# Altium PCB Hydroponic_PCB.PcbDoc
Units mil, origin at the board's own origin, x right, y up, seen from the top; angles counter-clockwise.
Board outline 3600 x 3940 mil, 4 copper layers (SIG 1, GND, SIG 2, PWR), stack 62.508 mil thick; 31 components, 21 nets, 122 pads, 71 vias.
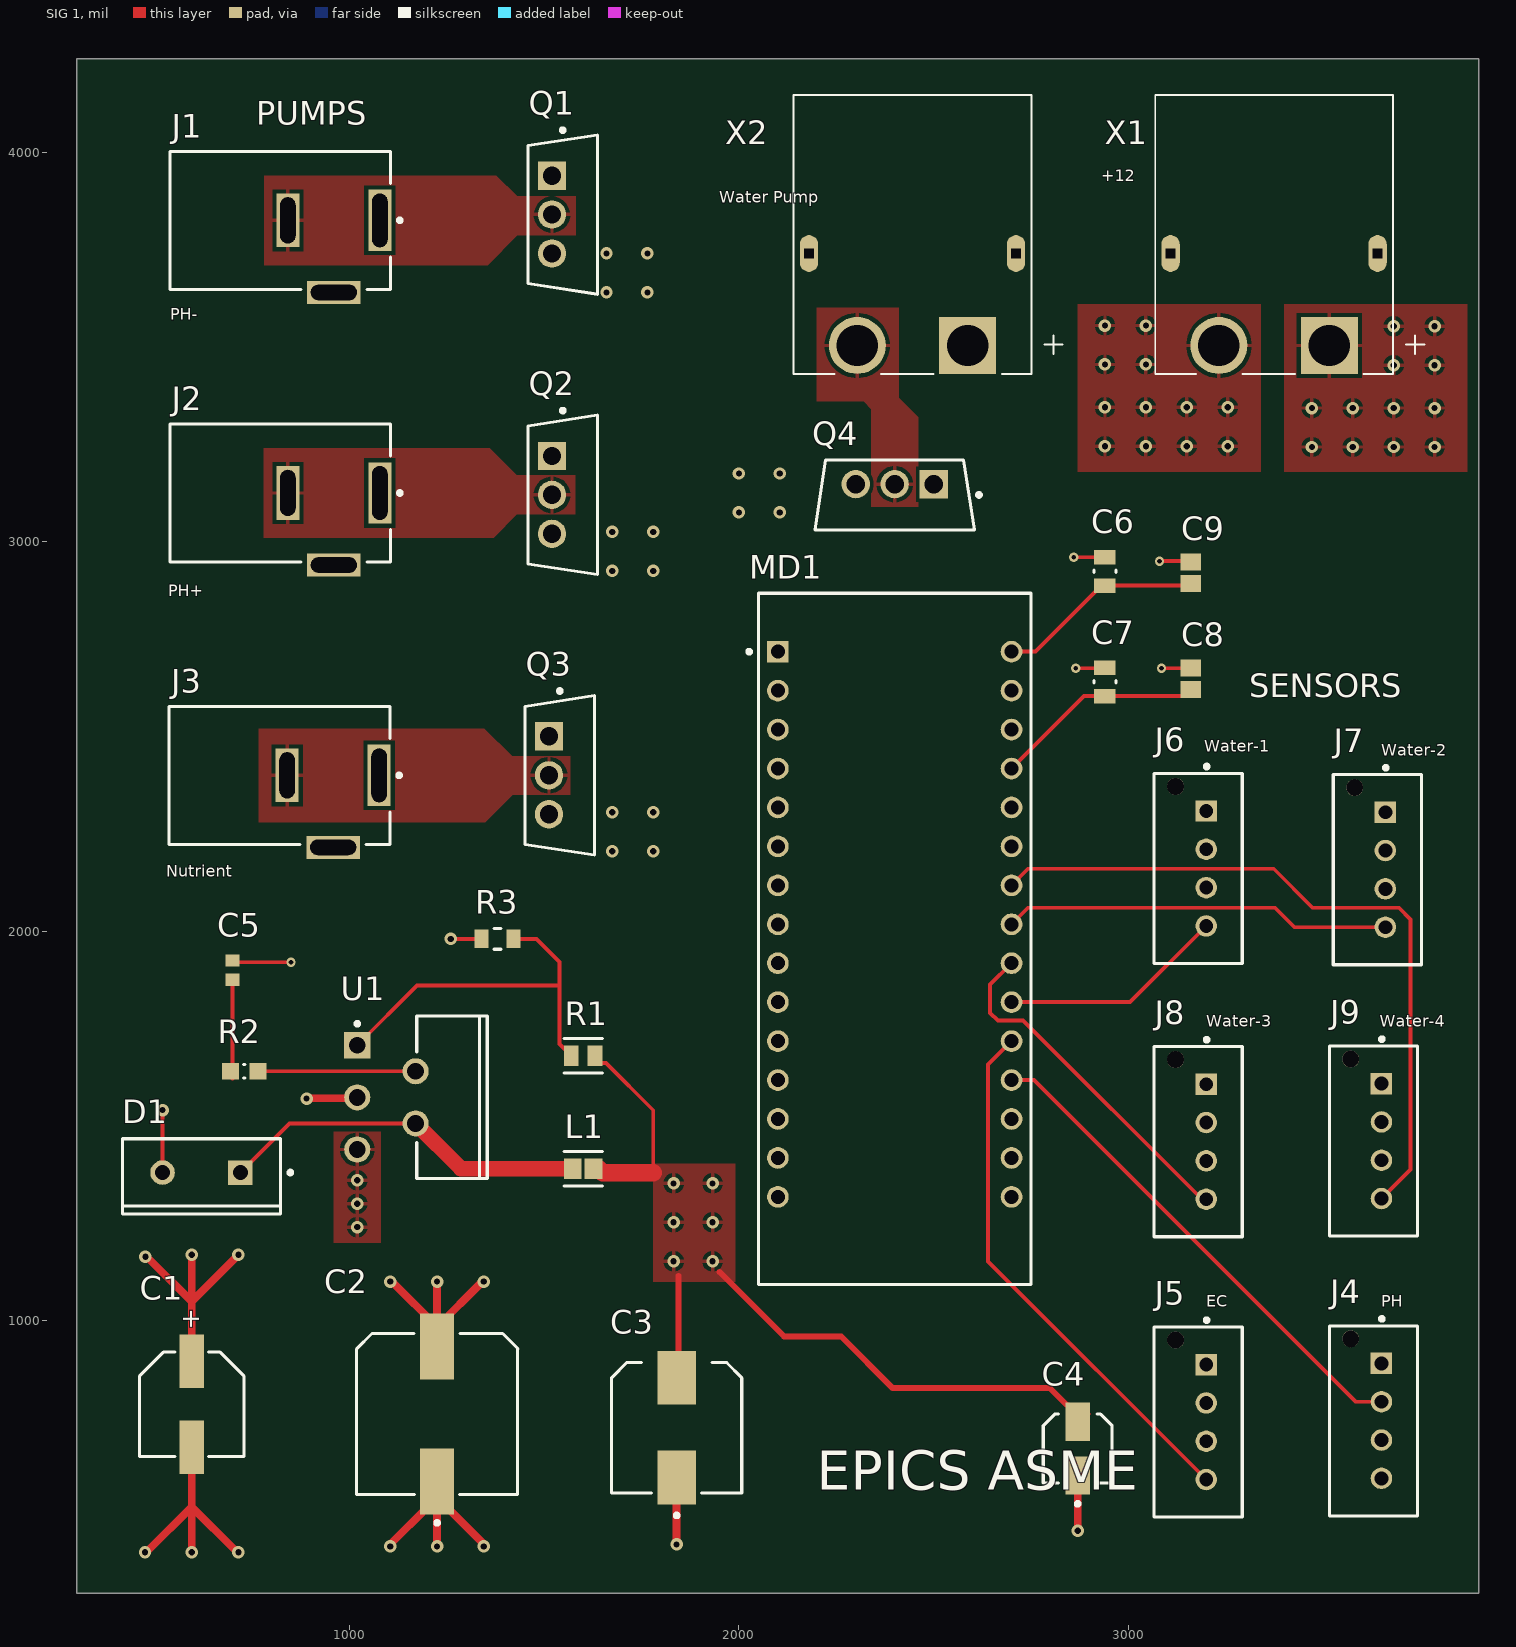
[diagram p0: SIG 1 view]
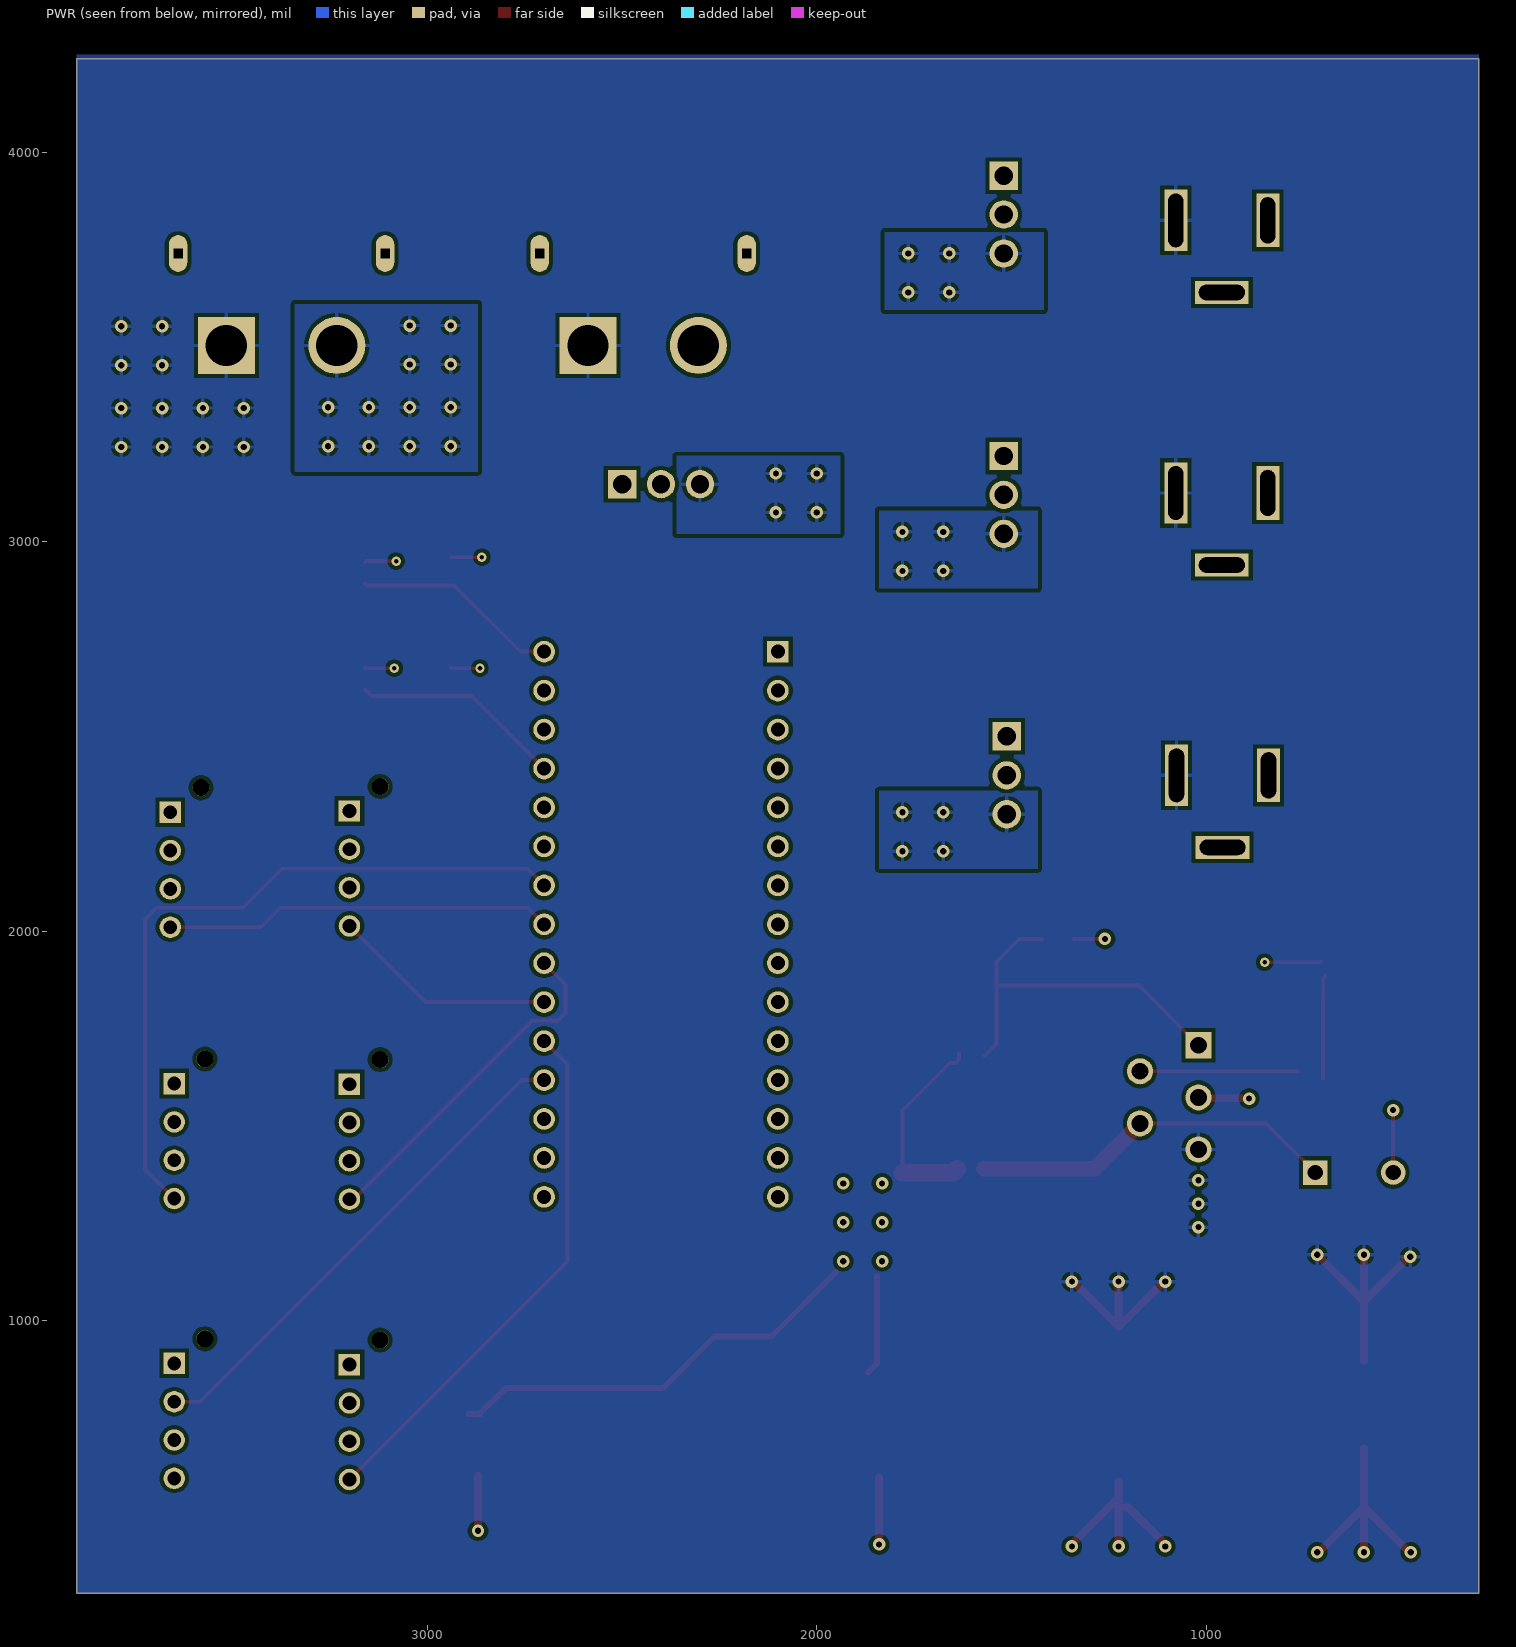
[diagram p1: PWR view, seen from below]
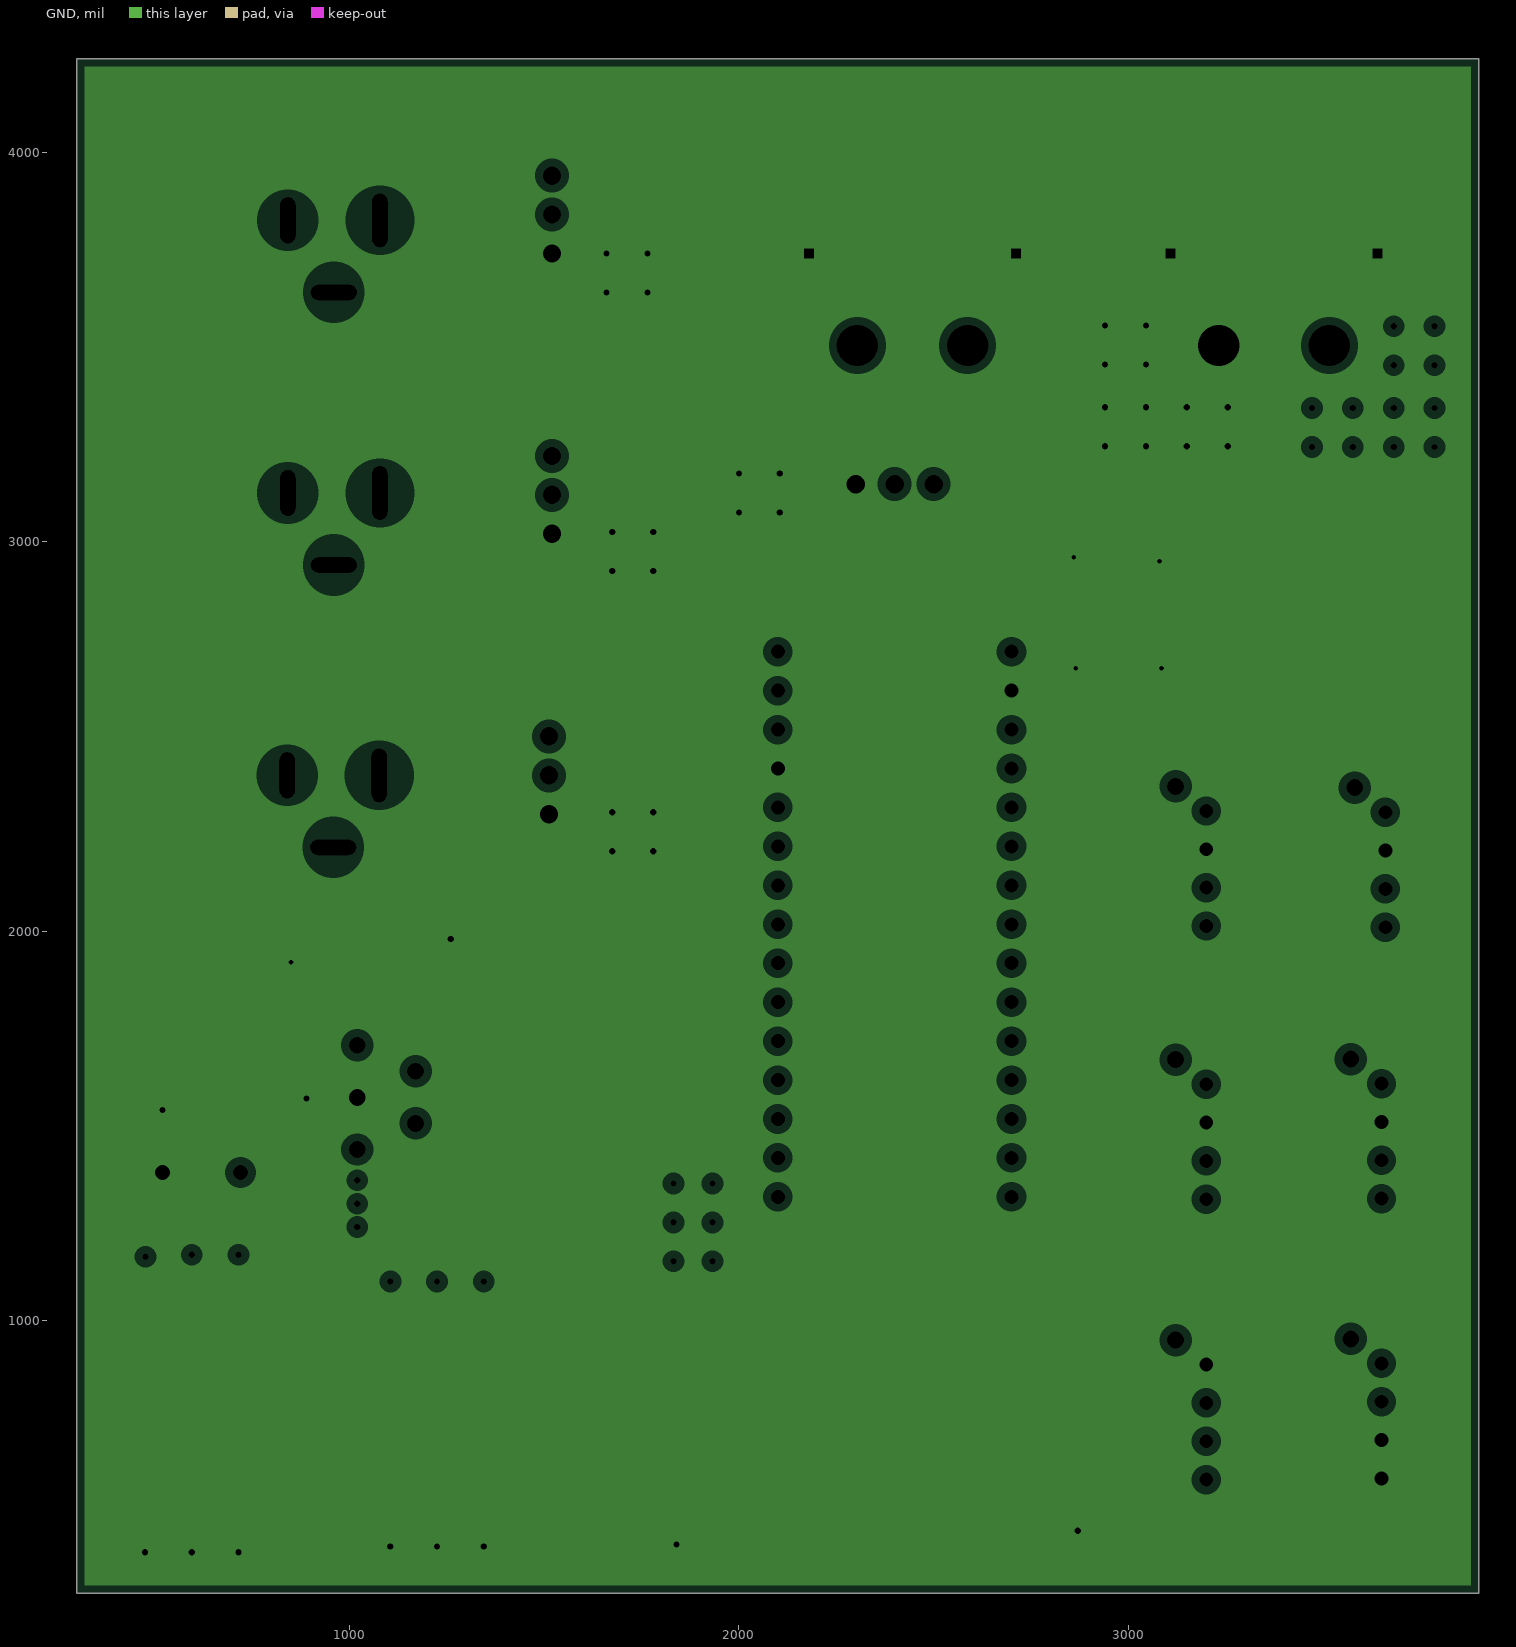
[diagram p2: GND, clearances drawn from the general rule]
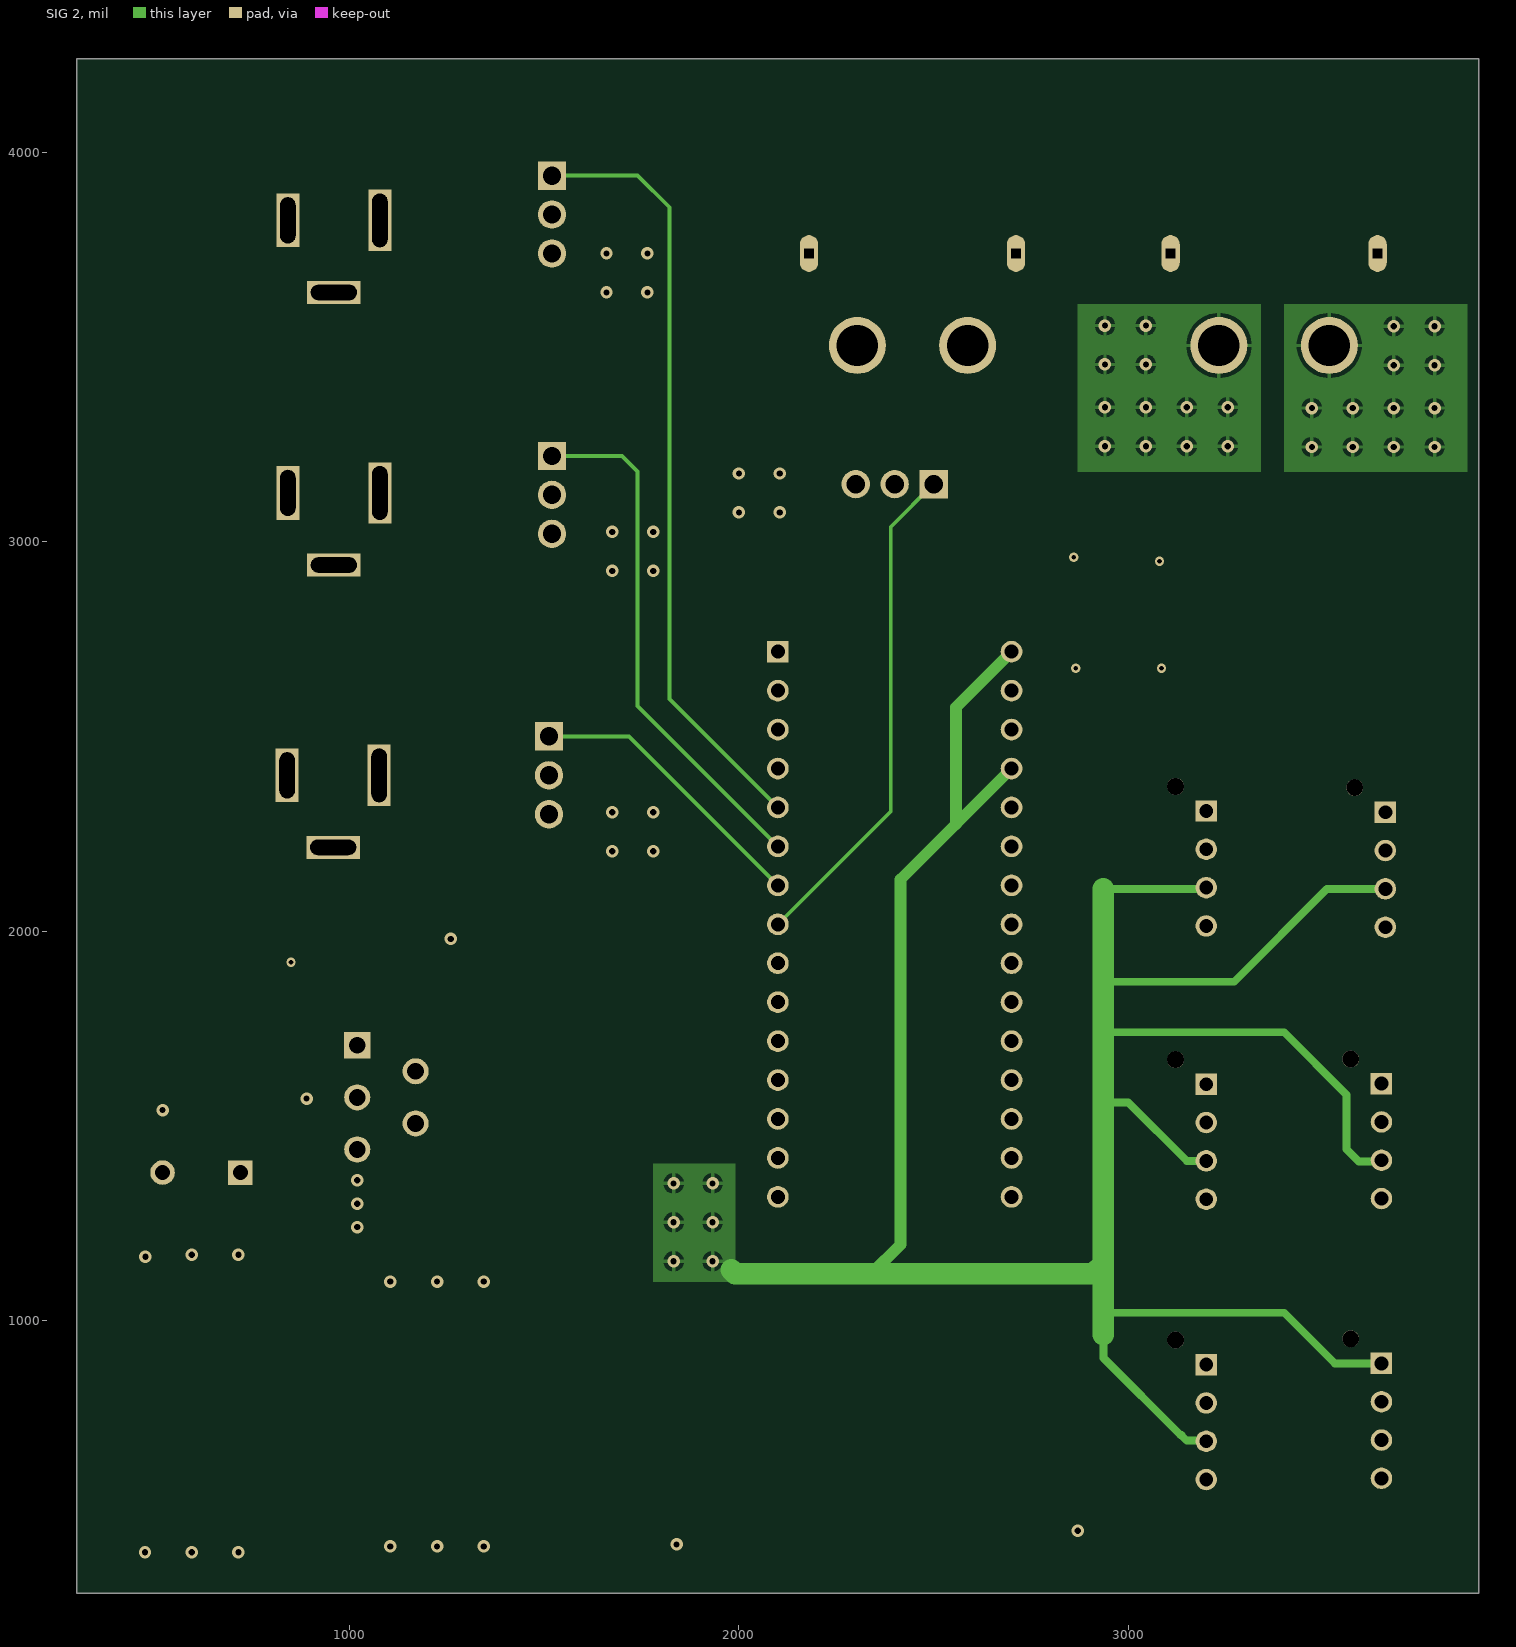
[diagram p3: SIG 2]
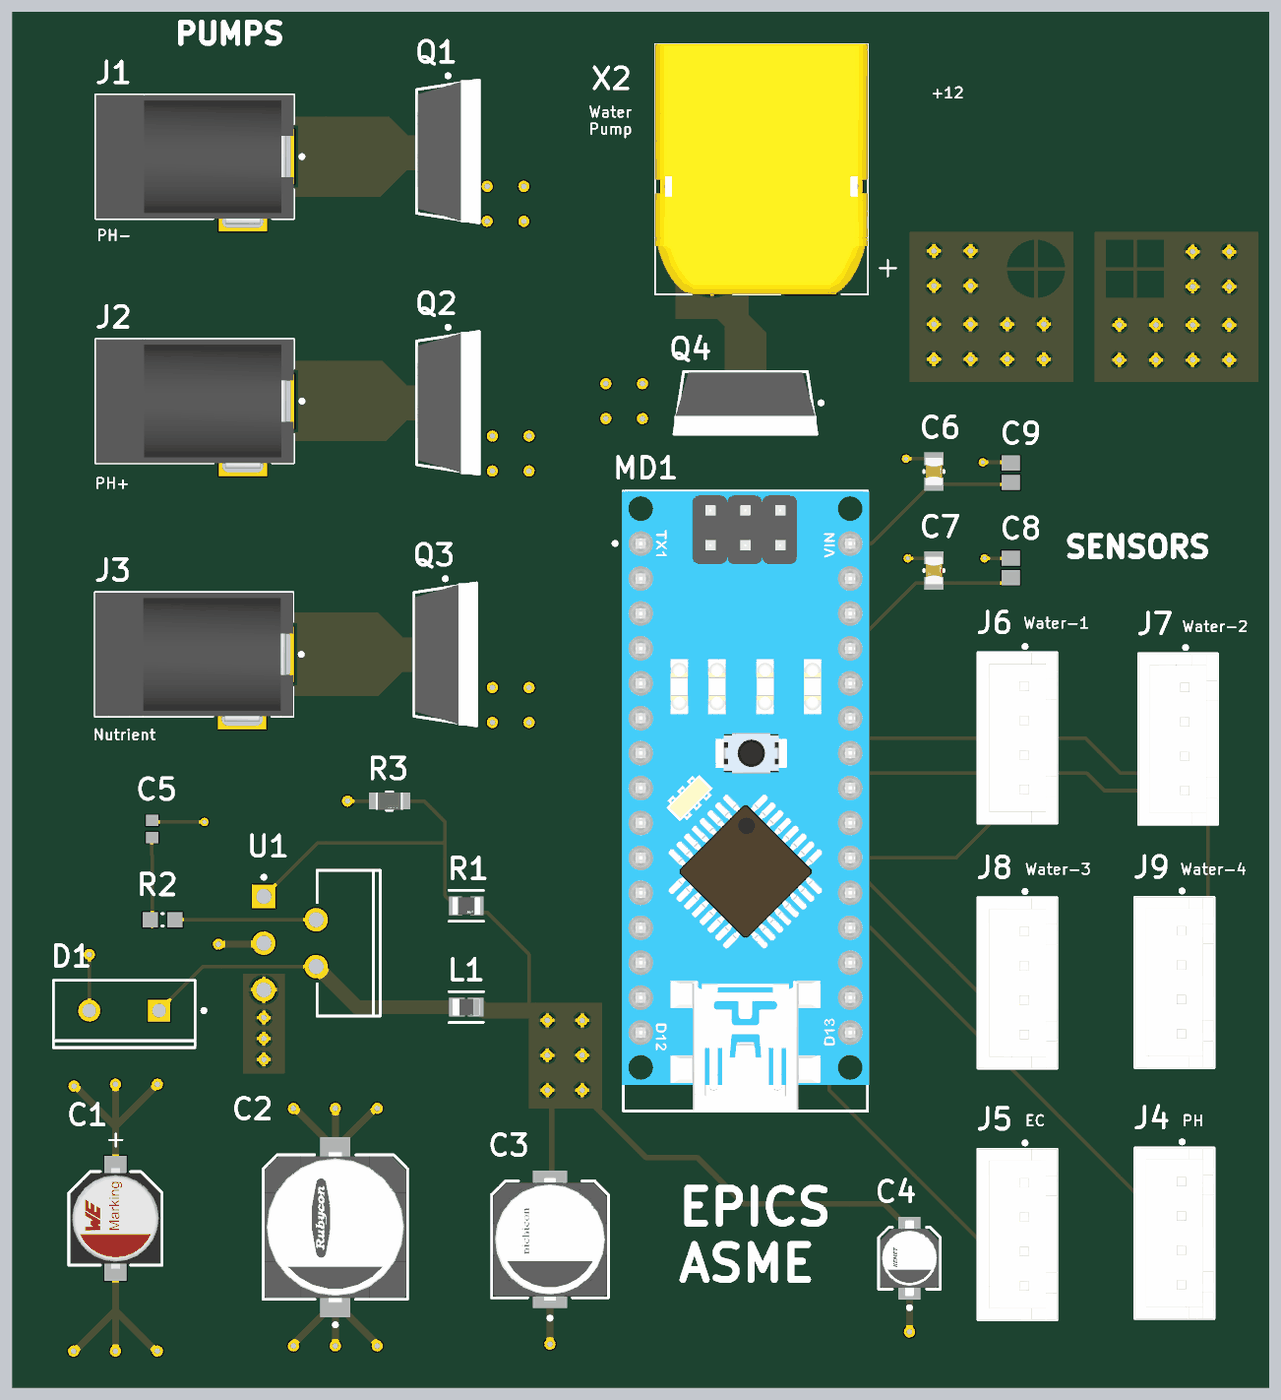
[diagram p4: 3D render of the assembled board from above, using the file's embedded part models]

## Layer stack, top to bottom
Top Solder: solder mask 0.4, Solder Resist, Dk 3.5
SIG 1: signal copper 1.4
Dielectric 1: prepreg 8.2, 7628, Dk 4.5
GND: plane copper 0.689, net GND
Dielectric 2: core 41.93, S1000-2M, Dk 4.3
SIG 2: signal copper 0.689
Dielectric 3: prepreg 8.2, 7628, Dk 4.5
PWR: signal copper 1.4
Bottom Solder: solder mask 0.4, Solder Resist, Dk 3.5

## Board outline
300,300 300,4240 3900,4240 3900,300

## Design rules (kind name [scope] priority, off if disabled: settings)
Clearance Components [InComponent('L1') OR InComponent('C5') OR InComponent('C8') OR InComponent('C9') OR InComponent('R2')] p1: gap=2 ignorepadtopadclearanceinfootprint=FALSE
Clearance GND_clearance [OnLayer('GND')] p2: gap=10 ignorepadtopadclearanceinfootprint=FALSE
Clearance [All] p3: gap=10 ignorepadtopadclearanceinfootprint=FALSE
HoleSize [All] p1: absolutevalues=TRUE maxlimit=150 minlimit=1 maxpercent=80.000 minpercent=20.000
MinimumSolderMaskSliver [All] p1: minsoldermaskwidth=3
PlaneClearance [All] p1: clearance=20
PlaneConnect [All] p1: planeconnectstyle=Relief reliefexpansion=20 reliefentries=4 reliefconductorwidth=10 reliefairgap=10
PolygonConnect [All] p1: connectstyle=Relief reliefconductorwidth=10 reliefentries=4 polygonreliefangle="90 Angle" airgapwidth=10
RoutingVias [All] p1: holewidth=12 width=24 viastyle="Through Hole" minholewidth=10 minwidth=18 maxholewidth=28 maxwidth=50
SilkToSolderMaskClearance [IsPad] p1: minsilkscreentomaskgap=3 clearancetoexposedcopper=TRUE
SolderMaskExpansion [All] p1: expansion=4 istentingtop=FALSE
SupplyNets "Schematic Supply Nets_2" [InNet('+12')] p1: voltage=0.000
SupplyNets "Schematic Supply Nets_1" [InNet('+5')] p2: voltage=0.000
SupplyNets "Schematic Supply Nets" [InNet('GND')] p3: voltage=0.000
Width [All] p1: maxlimit=100 minlimit=10 preferedwidth=10
25 further rules are at their usual default settings.

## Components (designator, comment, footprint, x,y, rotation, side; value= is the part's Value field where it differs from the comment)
C1 "220 uF" WCAP-ASLL_D6.3H7.7 595,785 r90 top
C2 "100 uF" FP-TGV10X10_5-MFG 1225,760 r90 top
C3 "47 uF" FP-UUX1H470MNL6GS-MFG 1840,725 r90 top
C4 "10 uF" FP-EDK9B-MFG 2870,671.1 r90 top value=10uF
C5 "10 nF" CAPC1608X87X35LL15T15 700,1900 r90 top
C6 "1 uF" FP-CC0805-0_85-MFG 2940,2923.58 r90 top
C7 "1 uF" FP-CC0805-0_85-MFG 2940,2640 r90 top
C8 "100 nF" CAPC2013X140X50LL20T25 3160,2647.56 r270 top
C9 "100 nF" CAPC2013X140X50LL20T25 3160,2920 r270 top
D1 "MBR745G" ONSC-TO-220-2-221B-04_E 620,1380 r270 top
J1 "PJ-002A" CUI-PJ-002A_V 960,3825.04 r180 top
J2 "PJ-002A" CUI-PJ-002A_V 960,3125.04 r180 top
J3 "PJ-002A" CUI-PJ-002A_V 958.11,2400 r180 top
J4 "PH Sensor Connector" FP-B4B-XH-AM_LF_SN-MFG 3629.33,742.36 r90 top
J5 "EC Sensor Connector" FP-B4B-XH-AM_LF_SN-MFG 3179.33,739.21 r90 top
J6 "Water sensor 1" FP-B4B-XH-AM_LF_SN-MFG 3179.33,2160.79 r90 top
J7 "Water sensor 3" FP-B4B-XH-AM_LF_SN-MFG 3639.33,2157.64 r90 top
J8 "Water sensor 2" FP-B4B-XH-AM_LF_SN-MFG 3179.33,1459.21 r90 top
J9 "Water sensor 4" FP-B4B-XH-AM_LF_SN-MFG 3629.33,1460.79 r90 top
L1 "100 uH" FP-LQM21DH_70-IPC_C 1600,1390 r0 top
MD1 "A000005" FP-A000005-MFG 2400,1980 r0 top
Q1 "IRLZ44NPbF" FP-PG-TO220-3-MFG 1547.76,3840 r0 top
Q2 "IRLZ44NPbF" FP-PG-TO220-3-MFG 1547.76,3120 r0 top
Q3 "IRLZ44NPbF" FP-PG-TO220-3-MFG 1540,2400 r0 top
Q4 "IRLZ44NPbF" FP-PG-TO220-3-MFG 2400,3120 r270 top
R1 "2.8k" FP-RG2012-IPC_C 1600,1680 r0 top
R2 "2.7k" RESC0603(1608)_M 730,1640 r0 top value="2700.00 Ohm"
R3 "2.2k" FP-AC0805-MFG 1380,1980 r0 top value=2.2KΩ
U1 "LT1076IT" LT-T-5-S 1095,1573.07 r0 top
X1 "X1" PCBComponent_1 4890.16,1901.26 r180 top
X2 "X2" PCBComponent_1 3961.65,1901.26 r180 top

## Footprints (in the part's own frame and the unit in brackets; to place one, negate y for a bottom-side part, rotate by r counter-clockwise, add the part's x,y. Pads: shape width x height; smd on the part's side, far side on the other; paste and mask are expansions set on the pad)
CAPC1608X87X35LL15T15 [mm] "Chip Capacitor, 2-Leads, Body 1.60x0.80mm, IPC High Density"
  rect 0.8x0.9 smd: 1(-0.625,0) 2(0.625,0)
  body extent -0.87,-0.48 0.87,0.48, height 0.87
CAPC2013X140X50LL20T25 [mm] "Chip Capacitor, 2-Leads, Body 2.00x1.25mm, IPC High Density"
  rect 1.1x1.35 smd: 1(-0.7,0) 2(0.7,0)
  body extent -1.1,-0.72 1.1,0.72, height 1.4
CUI-PJ-002A_V [mm] "THD, 3-Leads, Body 14.4x9mm, Height 11mm"
  rect 1.5x4 hole 1 slot 3.5 at 90 deg: 1(-3,0)
  rect 1.5x3.5 hole 1 slot 3 at 90 deg: 2(3,0)
  rect 3.5x1.5 hole 1 slot 3 at 0 deg: 3(0,4.7)
  silkscreen extent -4.43,-4.5 10.7,4.5, body extent -3.7,-4.5 10.7,4.9, height 11
FP-A000005-MFG [mil]
  rect 55.67x55.67 hole 35.98 paste-99999 mask+0: 1(-300,737.5)
  round 55.67 hole 35.98 paste-99999 mask+0: 2(-300,637.5) 3(-300,537.5) 4(-300,437.5) 5(-300,337.5) 6(-300,237.5) 7(-300,137.5) 8(-300,37.5) 9(-300,-62.5) 10(-300,-162.5) 11(-300,-262.5) 12(-300,-362.5) 13(-300,-462.5) 14(-300,-562.5) 15(-300,-662.5) 16(300,-662.5) 17(300,-562.5) 18(300,-462.5) 19(300,-362.5) 20(300,-262.5) 21(300,-162.5) 22(300,-62.5) 23(300,37.5) 24(300,137.5) 25(300,237.5) 26(300,337.5) 27(300,437.5) 28(300,537.5) 29(300,637.5) 30(300,737.5)
  silkscreen extent -379,-888 350,888, body extent -354,-891 354,891, height 10
FP-AC0805-MFG [mm]
  rect 0.9x1.2 smd paste+0 mask+0: 1(-1.05,0) 2(1.05,0)
  silkscreen extent -0.23,-0.67 0.23,0.67, body extent -1.6,-0.77 1.6,0.77, height 0.25
FP-B4B-XH-AM_LF_SN-MFG [mm]
  rect 1.4x1.4 hole 0.9 paste-2539.97 mask+0: 1(3.75,-0.525)
  round 1.4 hole 0.9 paste-2539.97 mask+0: 2(1.25,-0.525) 3(-1.25,-0.525) 4(-3.75,-0.525)
  round 1.1 hole 1.1 unplated paste-2539.97 mask+0: ""(5.35,1.475)
  silkscreen extent -6.2,-2.88 6.77,2.88, body extent -6.3,-2.98 6.3,2.98, height 0.25
FP-CC0805-0_85-MFG [mm]
  rect 0.95x1.4 smd paste+0 mask+0: 1(-0.925,0) 2(0.925,0)
  silkscreen extent -0.08,-0.72 0.08,0.72, body extent -1.6,-1.05 1.6,1.05, height 0.25
FP-EDK9B-MFG [mm]
  rect 2.5x1.6 smd paste+0 mask+0: 1(-1.75,0) 2(1.75,0)
  silkscreen extent -3.72,-2.25 2.25,2.25, body extent -3.25,-2.5 3.25,2.5, height 0.25
FP-LQM21DH_70-IPC_C [mil]
  rect 45.45x53.39 smd paste+0 mask+0: 1(-26.61,0) 2(26.61,0)
  silkscreen extent -49,-44 49,44, body extent -53,-32 53,32, height 10
FP-PG-TO220-3-MFG [mm]
  rect 1.85x1.85 hole 1.2 paste-2539.97 mask+0: 1(-0.705,2.54)
  round 1.85 hole 1.2 paste-2539.97 mask+0: 2(-0.705,0) 3(-0.705,-2.54)
  silkscreen extent -2.27,-5.2 2.27,5.62, body extent -2.37,-5.55 2.37,5.55, height 0.25
FP-RG2012-IPC_C [mil]
  rect 37.59x53.39 smd paste+0 mask+0: 1(-30.54,0) 2(30.54,0)
  silkscreen extent -49,-44 49,44, body extent -53,-32 53,32, height 10
FP-TGV10X10_5-MFG [mm]
  rect 4.3x2.2 smd paste+0 mask+0: 1(-4.4,0) 2(4.4,0)
  silkscreen extent -7.22,-5.28 5.25,5.25, body extent -6.8,-5.5 6.8,5.5, height 0.25
FP-UUX1H470MNL6GS-MFG [mm]
  rect 3.5x2.5 smd paste+0 mask+0: 1(-3.25,0) 2(3.25,0)
  silkscreen extent -5.85,-4.25 4.26,4.25, body extent -5.25,-4.5 5.25,4.5, height 0.25
LT-T-5-S [mm] "FM, 5-Leads, Body 10.55x4.6mm, Pitch 1.7mm"
  rect 1.7x1.7 hole 1.1: 1(-1.905,3.4)
  round 1.7 hole 1.1: 2(1.905,1.7) 3(-1.905,0) 4(1.905,-1.7) 5(-1.905,-3.4)
  silkscreen extent -2.03,-5.3 6.58,5.3, body extent -2.13,-5.27 6.58,5.28, height 22.23
ONSC-TO-220-2-221B-04_E [mm] "FM, 2-Leads, Body 10.3x4.85mm, Pitch 5.08mm"
  rect 1.6x1.6 hole 1: 1(0,2.54)
  round 1.6 hole 1: 3(0,-2.54)
  silkscreen extent -2.2,-5.15 2.7,5.93, body extent -2.18,-5.15 2.67,5.15, height 19.05
PCBComponent_1 [mm]
  rect 3.716x3.716 / inner round 3.716 / far side rect 3.716x3.716 hole 2.7 mask+0.102: 1(34.904,-40.704)
  round 3.716 hole 2.7 mask+0.102: 2(42.104,-40.704)
  oval 1.2x2.4 hole 0.6 square mask+0.102: SH1(31.754,-46.704) SH2(45.254,-46.704)
  silkscreen extent 28.7,-57.05 46.25,-38.85, body extent 30.75,-57.05 46.25,-38.85, height 8.4
RESC0603(1608)_M [mm] "Chip Resistor, Body 1.6x0.8mm, IPC Low Density"
  rect 1.1x1.1 smd: 1(-0.9,0) 2(0.9,0)
  silkscreen extent -0.05,-0.45 0.05,0.45, body extent -0.85,-0.47 0.85,0.47, height 0.6
WCAP-ASLL_D6.3H7.7 [mm] "Aluminium Electrolytic V-Chip SMT Capacitors, 6.3x7.7mm"
  rect 3.5x1.6 smd: 1(2.8,0) 2(-2.8,0)
  silkscreen extent -3.4,-3.4 3.4,3.4, body extent -3.65,-3.3 3.65,3.3, height 7.7

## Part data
C1: library part CMP-03913-53914500-3, Capacitance=220µF, Case/Package=Radial, ESR (Equivalent Series Resistance)=246.927mΩ, Insulation Resistance=454.545kΩ, Leakage Current=13.86µA, Max Operating Temperature=105°C, Min Operating Temperature=-55°C, Ripple Current=280mA, Tolerance=20%, Voltage Rating=6.3V
C2: library part CMP-35376-000017-1, "CAP ALUM 100UF 20% 35V SMD"
C3: library part CMP-12462-000056-1, "CAP ALUM 47UF 20% 50V SMD", Capacitance=47uF, Case/Package=Radial, Leakage Current=70.5uA, Max Operating Temperature=105°C, Min Operating Temperature=-55°C, Package Quantity=1, Ripple Current=167mA, Tolerance=20%, Voltage=50V
C4: library part CMP-03015-000003-1, "CAP ALUM 10UF 20% 35V SMD", Capacitance=10uF, Leakage Current=3.5uA, Manufacturer=Kemet, Manufacturer Part Number=EDK106M035A9BAA, Package=EDK9B, Ripple Current=24mA, Temperature="-40°C to +85°C", Temperature Range High=+85°C, Temperature Range Low=-40°C, Tolerance=20%, Voltage Rating=35V
C5: library part CMP-2006-03842-1, Manufacturer=Kemet, Part Number=C0603S103K4RACTU
C6 C7: library part CMP-03422-000746-1, "CAP CER 1UF 10V X5R 0805", Manufacturer=Yageo, Manufacturer Part Number=CC0805KKX5R6BB105, Package=CC0805-0.85, Temperature="-30°C to +85°C", Temperature Characteristic=X5R, Temperature Range High=+85°C, Temperature Range Low=-30°C, Tolerance=0.1, Voltage Rating="10 V"
C8 C9: library part CMP-2007-04740-1, Manufacturer="AVX Interconnect / Elco", Part Number=08051C104M4Z2A
D1: library part CMP-1055-00593-1, "SWITCHMODE(TM) Power Rectifier, 2-Pin TO-220, Pb-Free, Tube", Manufacturer="On Semiconductor"
J1 J2 J3: library part CMP-2000-06895-2, "Through Hole Right Angle DC Power Jack, 2.5 A, 2 mm Center Pin, 3 Position, -25 to 85 degC, RoHS, Bulk", Current Rating=2.5A, Flammability Rating=UL94V-0, Insulation Resistance=50MOhms, Manufacturer=CUIInc., Operating Temperature Range=-25Cto+85C, Package Description="3-Pin Through Hole Device, Body 14.4 x 9 mm, Height 11 mm", Voltage Rating=24V
J4 J5 J6 J7 J8 J9: library part CMP-17439-000117-1, "CONN HEADER VERT 4POS 2.5MM", Color=Green, Contact Resistance=20mR, Flammability Rating="UL94 V-0", Housing Color=White, Insulation Color=Natural, Max Current Rating=3A, Max Operating Temperature=85°C, Max Voltage Rating (AC)=250V, Min Operating Temperature=-25°C
L1: library part CMP-06042-017057-1, "Multilayer type Inductor for Power Lines for Automotive 100uH ±20% @1MHz, 160mA, Max DCR 4.095Ω, SRF 8MHz"
MD1: library part CMP-189986-000002-1, "ARDUINO NANO ATMEGA328 EVAL BRD", Operating Supply Voltage=12V, Package Quantity=50
Q1 Q2 Q3 Q4: library part CMP-32901-000488-1, "MOSFET N-CH 55V 47A TO220AB", Case/Package=TO-220, Continuous Drain Current (ID)=47A, Drain to Source Breakdown Voltage=55V, Drain to Source Resistance=35mR, Gate to Source Voltage (Vgs)=16V, Input Capacitance=1.7nF, Max Operating Temperature=175°C, Max Power Dissipation=110W, Min Operating Temperature=-55°C, Threshold Voltage=2V
R1: library part CMP-28537-010746-1, "Automotive Metal Thin Film Chip Resistor, 0805, 2.8kΩ, 0.1%, 25ppm/°C, 0.125W, 150V", Case Code (Imperial)=0805, Case Code (Metric)=2012, Max Operating Temperature=155°C, Max Power Dissipation=125mW, Min Operating Temperature=-55°C, Package Quantity=5000, Resistance=2.8kR, Resistor Type="Thin Film", Temperature Coefficient=25ppm/°C, Tolerance=0.1%, Voltage Rating=150V
R2: library part CMP-1012-00084-1, "2K7 0.1W 5% 0603 (1608 Metric)  SMD", Case-EIA=0603, Case-Metric=1608, Power="0.1 W", Tolerance="5 %"
R3: library part CMP-03412-037614-1, "RES SMD 2.2K OHM 5% 1/8W 0805", Manufacturer=Yageo, Manufacturer Part Number=AC0805JR-072K2L, Package=AC0805, Power Rating=1/8W, Resistance=2.2KΩ, Temperature="-55°C to +155°C", Temperature Range High=+155°C, Temperature Range Low=-55°C, Tolerance=0.05, Voltage Rating=150V
U1: library part CMP-0491-02059-1, "Step-Down Switching Regulator, 5-pin FM (T-5), -40 to 85 degC", Manufacturer="Linear Technology"
X1 X2: library part xt60

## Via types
v1: diameter 32, hole 16, SIG 1 to PWR, 66 vias
v2: diameter 24, hole 12, SIG 1 to PWR, 5 vias

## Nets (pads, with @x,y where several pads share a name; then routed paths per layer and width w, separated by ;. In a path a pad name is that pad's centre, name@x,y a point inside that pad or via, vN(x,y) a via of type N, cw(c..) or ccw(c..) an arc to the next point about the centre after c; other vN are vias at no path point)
+5: C3.2 C4.2 C6.1 C7.1 C8.2 C9.2 J4.1 J5.3 J6.3 J7.3 J8.3 J9.3 L1.2 MD1.27 MD1.30 R1.2 | length 10556.7
  SIG 1 w10: R1.2@1634.66,1685.34 1634.66,1671.2 1644.33,1661.52 1658.48,1661.52 1780,1540 1780,1380 ; MD1.27 2886.08,2603.58 C7.1 3143.58,2603.58 C8.2 ; MD1.30 2761.48,2717.5 2931.14,2887.17 C6.1 3154.72,2887.17 C9.2
  SIG 1 w15: 1845,1115 1845,890 C3.2@1869,866 ; 1949.95,1125.05 2116.18,958.82 2262.76,958.82 2395.19,826.39 2798.61,826.39 2843.29,781.71 2846,781.71 2865,762.72 2865,760 C4.2@2895,760
  SIG 1 w45: L1.2@1640,1390 1650,1380 1780,1380
  SIG 2 w20: 2936.05,963.95 2936.05,903.95 3134.24,705.76 3136.19,705.76 3150.38,691.57 J5.3@3200,691.57 ; 2936.05,1020 3400,1020 3530,890 J4.1 ; 2936.05,1560 3000,1560 3150,1410 J8.3 ; 2936.05,1740 3400,1740 3560,1580 3560,1440 3591.57,1408.43 J9.3@3660,1408.43 ; 2936.05,1870 3271.57,1870 3510,2108.43 J7.3 ; 2936.05,2108.43 3200,2108.43 J6.3@3206.22,2108.43
  SIG 2 w30: 2340,1120 2415,1195 2415,2132.5 2557.5,2275 ; MD1.27 2557.5,2275 ; MD1.30 2557.5,2575 2557.5,2275
  SIG 2 w55: 1980,1130 1990,1120 2340,1120 2910,1120 2936.05,1146.05 ; 2936.05,963.95 2936.05,1020 2936.05,1146.05 ; 2936.05,2108.43 2936.05,1870 2936.05,1740 2936.05,1560 2936.05,1146.05
  other v1: 1832.34,1152.11 1932.34,1152.11 1832.34,1252.11 1932.34,1252.11 1832.34,1352.11 1932.34,1352.11
+12: C1.1 C2.2 J1.1 J2.1 J3.1 U1.5 X1.1 X2.1 | length 1064.4
  SIG 1 w20: v1@475,1165 v1(476.15,1163.85) 477.3,1162.7 481.08,1162.7 595,1048.78 ; C1.1 595,1048.78 ; v1(595,1169.06) 595,1048.78 ; v1(715,1169.06) 715,1168.78 595,1048.78 ; v1(1105,1100) 1107.3,1097.7 1111.08,1097.7 C2.2@1225,983.78 ; v1(1225,1100) C2.2@1225,983.78 ; v1(1345,1100) 1342.7,1097.7 1338.92,1097.7 C2.2@1225,983.78
  other v1: 1020,1240 1020,1300 1020,1360 3471.31,3243.08 3576.31,3243.08 3681.31,3243.08 3786.31,3243.08 3471.31,3343.08 3576.31,3343.08 3681.31,3343.08 3786.31,3343.08 3681.31,3453.08 3786.31,3453.08 3681.31,3553.08 3786.31,3553.08
A_EC: J5.4 MD1.20 | length 1382.7
  SIG 1 w10: MD1.20 2640,1657.5 2640,1151.57 J5.4
GND: C1.2 C2.1 C3.1 C4.1 C5.2 C6.2 C7.2 C8.1 C9.1 D1.3 J4.3 J4.4 J5.1 J6.2 J7.2 J8.2 J9.2 MD1.4 MD1.29 Q1.3 Q2.3 Q3.3 Q4.3 R3.1 U1.3 X1.2 X1.SH1 X1.SH2 X2.SH1 X2.SH2 | length 2251.4
  SIG 1 w10: D1.3 v1@520,1540 ; C5.2@705.21,1920.29 705.51,1920 v2(850,1920) ; v1(1260,1980) R3.1 R3.1@1339.33,1979.33 ; v2(2860,2960) C6.2 ; v2(2865,2675) 2938.58,2675 C7.2 ; v2(3080,2950) 3157.56,2950 C9.1 ; v2(3085,2675) 3159.88,2675 C8.1
  SIG 1 w20: v1(475,405) 477.3,407.3 481.08,407.3 595,521.22 ; v1(595,405) 595,521.22 ; C1.2@595,671.91 595,521.22 ; v1(715,405) 712.7,407.3 708.92,407.3 595,521.22 ; v1(890,1570) 890.77,1570.77 1017.69,1570.77 U1.3 ; v1(1105,420) 1107.3,422.3 1107.3,427.73 1199.57,520 C2.1@1225,520 ; v1(1225,420) C2.1@1225,520 ; C2.1 C2.1@1225,545.43 ; v1(1345,420) 1342.7,422.3 1342.7,427.73 C2.1@1225,545.43 ; v1(1840,425) C3.1 ; v1(2870,460) C4.1 ; C2.1@1225,520 C2.1@1225,545.43
  other v1: 520.09,1540.5 1675,2205 1780,2205 1675,2305 1780,2305 1675,2925 1780,2925 1675,3025 1780,3025 2000,3075 2105,3075 2000,3175 2105,3175 2940,3245 3045,3245 3150,3245 3255,3245 2940,3345 3045,3345 3150,3345 3255,3345 2940,3455 3045,3455 2940,3555 3045,3555 1660,3640 1765,3640 1660,3740 1765,3740
NetC5_1: C5.1 R2.1 | length 267.2
  SIG 1 w10: C5.1@695,1885 699.57,1880.43 699.57,1824.96 700,1825.39 R2.1@700,1620.78
NetD1_1: D1.1 L1.1 U1.4 | length 951
  SIG 1 w10: D1.1 846.14,1506.14 U1.4
  SIG 1 w40: U1.4 1286.14,1390 L1.1@1570.67,1390
NetJ1_2: J1.2 Q1.2
NetJ2_2: J2.2 Q2.2
NetJ3_2: J3.2 Q3.2
NetQ4_2: Q4.2 X2.2
NetR1_1: R1.1 R3.2 U1.1 | length 978
  SIG 1 w10: U1.1 1173.07,1860 1538.93,1860 ; R3.2 1480,1980 1538.93,1921.07 1538.93,1860 ; R1.1 1538.93,1710.54 1538.93,1860
NetR2_2: R2.2 U1.2 | length 404.6
  SIG 1 w10: R2.2 U1.2
PO_PH: J4.2 MD1.19 | length 1292.1
  SIG 1 w10: MD1.19 2757.5,1617.5 3583.43,791.57 J4.2
"Pump (Gro)": MD1.7 Q3.1 | length 746.2
  SIG 2 w10: Q3.1 1717.5,2500 MD1.7
"Pump (PH+)": MD1.6 Q2.1 | length 1348.2
  SIG 2 w10: Q2.1 1700,3220 1740,3180 1740,2577.5 MD1.6
"Pump (PH-)": MD1.5 Q1.1 | length 1991.6
  SIG 2 w10: Q1.1 1740,3940 1821.34,3858.66 1821.34,2596.16 MD1.5
"Pump (Water)": MD1.8 Q4.1 | length 1295.9
  SIG 2 w10: MD1.8 2390,2307.5 2390,3037.76 Q4.1
WaterS_1: J6.4 MD1.21 | length 581
  SIG 1 w10: MD1.21 3004.35,1817.5 J6.4
WaterS_2: J8.4 MD1.22 | length 903.5
  SIG 1 w10: MD1.22 2645,1862.5 2645,1790 2665,1770 2730,1770 3188.43,1311.57 J8.4
WaterS_3: J7.4 MD1.23 | length 998.3
  SIG 1 w10: MD1.23 2742.5,2060 3377.1,2060 3427.1,2010 J7.4
WaterS_4: J9.4 MD1.24 | length 1844.4
  SIG 1 w10: MD1.24 2742.5,2160 3373.35,2160 3473.35,2060 3695,2060 3725,2030 3725,1388.15 J9.4
pads on no net: J1.3 J2.3 J3.3 J4. J5. J5.2 J6. J6.1 J7. J7.1 J8. J8.1 J9. J9.1 MD1.1 MD1.2 MD1.3 MD1.9 MD1.10 MD1.11 MD1.12 MD1.13 MD1.14 MD1.15 MD1.16 MD1.17 MD1.18 MD1.25 MD1.26 MD1.28

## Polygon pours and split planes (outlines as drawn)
+12 on SIG 1 "+12_L01_P017" (solid, remove dead copper, pour order 17): 3400,3610 3870,3610 3870,3180 3400,3180
GND on SIG 1 "GND_L01_P014" (solid, remove dead copper, pour order 14): 2870,3610 3340,3610 3340,3180 2870,3180
NetQ4_2 on SIG 1 "NETQ4_2_L01_P010" (solid, remove dead copper, pour order 10): 2200,3600 2200,3360 2320,3360 2340,3340 2340,3090 2460,3090 2460,3320 2410,3370 2410,3600
NetJ1_2 on SIG 1 "NETJ1_2_L01_P005" (solid, remove dead copper, pour order 5): 781.1,3710 1354.79,3710 1431.1,3786.31 1581.1,3786.31 1581.1,3886.31 1431.1,3886.31 1377.41,3940 781.1,3940
NetJ2_2 on SIG 1 "NETJ2_2_L01_P003" (solid, remove dead copper, pour order 3): 780,3010 1370,3010 1430,3070 1580,3070 1580,3170 1430,3170 1360,3240 780,3240
NetJ3_2 on SIG 1 "NETJ3_2_L01_P004" (solid, remove dead copper, pour order 4): 767.36,2280 1348.66,2280 1418.66,2350 1567.36,2350 1567.36,2448.7 1417.36,2448.7 1346.06,2520 767.36,2520
+5 on SIG 1 "+5_L01_P001" (solid, remove dead copper, pour order 1): 1780,1402.5 1990,1402.5 1990,1100 1780,1100
+12 on SIG 1 "+12_L01_P000" (solid, remove dead copper, pour order 0): 960,1485 1080,1485 1080,1200 960,1200
+12 on SIG 2 "+12_L03_P016" (solid, remove dead copper, pour order 16): 3400,3610 3870,3610 3870,3180 3400,3180
GND on SIG 2 "GND_L03_P015" (solid, remove dead copper, pour order 15): 2870,3610 3340,3610 3340,3180 2870,3180
+5 on SIG 2 "+5_L03_P002" (solid, remove dead copper, pour order 2): 1780,1402.5 1990,1402.5 1990,1100 1780,1100
+12 on PWR "+12_L04_P013" (solid, remove dead copper, pour order 13): 300,4250 3900,4250 3900,300 300,300
GND on PWR "GND_L04_P012" (solid, remove dead copper, pour order 12): 2870,3610 2870,3180 3340,3180 3340,3610
GND on PWR "GND_L04_P011" (solid, remove dead copper, pour order 11): 2360,3220 1940,3220 1940,3020 2360,3020
GND on PWR "GND_L04_P009" (solid, remove dead copper, pour order 9): 1417.5,3780 1417.5,3595 1825,3595 1825,3795 1417.5,3795
GND on PWR "GND_L04_P008" (solid, remove dead copper, pour order 8): 1432.5,3065 1432.5,2880 1840,2880 1840,3080 1432.5,3080
GND on PWR "GND_L04_P007" (solid, remove dead copper, pour order 7): 1432.5,2345 1432.5,2160 1840,2160 1840,2360 1432.5,2360
GND on GND (split plane): 3879.9,320.1 320.1,320.1 320.1,4219.9 3879.9,4219.9

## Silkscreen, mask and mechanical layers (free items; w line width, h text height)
Top Overlay:
  text "PUMPS" at 760,4070 h60
  text "+12" at 2930,3925 h30
  text "Water Pump" at 1950,3870 h30
  text "PH-" at 540,3570 h30
  text "PH+" at 535,2860 h30
  text "SENSORS" at 3310,2600 h60
  text "Water-1" at 3195,2460 h30
  text "Water-2" at 3650,2450 h30
  text "Nutrient" at 530,2140 h30
  text "Water-3" at 3200,1755 h30
  text "Water-4" at 3645,1755 h30
  text "EC" at 3200,1035 h30
  text "PH" at 3650,1035 h30
  text "EPICS ASME" at 2200,565 h100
